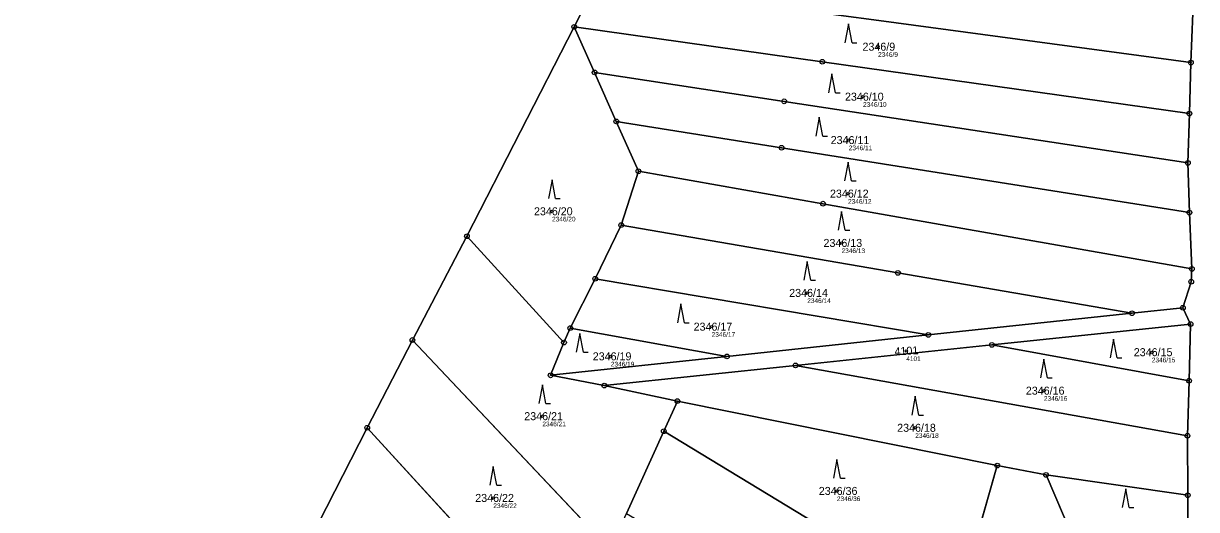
# Model space of a CAD drawing. Extents: x -658203 to -653176, y -1156738 to -1151709.
# Drawn here: x -657305.7 to -657056.4, y -1156494.1 to -1156390.7 of the extents above; entities that cross this region are included whole.
import ezdxf

# ---------------------------------------------------------------- set-up
doc = ezdxf.new("R2010")
doc.units = 0
for name, color, linetype in [('Vrstva 1', 7, 'Continuous'), ('Vrstva 2', 7, 'Continuous'), ('Vrstva 3', 7, 'Continuous'), ('Vrstva 50', 7, 'Continuous'), ('Vrstva 51', 7, 'Continuous'), ('Vrstva 8', 7, 'Continuous')]:
    doc.layers.add(name, color=color, linetype=linetype)

msp = doc.modelspace()

# ---------------------------------------------------------------- linework, layer by layer
at = {"layer": 'Vrstva 1'}
for p, q in [((-657188.62, -1156391.4), (-657183.91, -1156382.03)), ((-657057.61, -1156399.01), (-657057.22, -1156388.52)), ((-657211.43, -1156435.94), (-657188.62, -1156391.4)), ((-657188.62, -1156391.4), (-657184.31, -1156401.1)), ((-657057.94, -1156409.86), (-657057.61, -1156399.01)), ((-657184.31, -1156401.1), (-657179.69, -1156411.51)), ((-657058.25, -1156420.34), (-657057.94, -1156409.86)), ((-657179.69, -1156411.51), (-657174.98, -1156422.11)), ((-657057.94, -1156430.9), (-657058.25, -1156420.34)), ((-657178.65, -1156433.58), (-657174.98, -1156422.11)), ((-657057.41, -1156442.87), (-657057.94, -1156430.9)), ((-657184.17, -1156444.97), (-657178.65, -1156433.58)), ((-657223, -1156458.01), (-657211.43, -1156435.94)), ((-657211.43, -1156435.94), (-657190.81, -1156458.55)), ((-657189.48, -1156455.46), (-657184.17, -1156444.97)), ((-657184.17, -1156444.97), (-657113.4, -1156456.93)), ((-657113.4, -1156456.93), (-657070.13, -1156452.33)), ((-657070.13, -1156452.33), (-657059.32, -1156451.14)), ((-657059.32, -1156451.14), (-657057.68, -1156454.62)), ((-657190.81, -1156458.55), (-657189.48, -1156455.46)), ((-657189.48, -1156455.46), (-657156.18, -1156461.51)), ((-657057.68, -1156454.62), (-657099.89, -1156459.04)), ((-657057.68, -1156454.62), (-657058.01, -1156466.67)), ((-657232.62, -1156476.67), (-657223, -1156458.01)), ((-657223, -1156458.01), (-657180.99, -1156502.54)), ((-657156.18, -1156461.51), (-657113.4, -1156456.93)), ((-657193.65, -1156465.52), (-657190.81, -1156458.55)), ((-657099.89, -1156459.04), (-657141.61, -1156463.43)), ((-657099.89, -1156459.04), (-657058.01, -1156466.67)), ((-657193.65, -1156465.52), (-657156.18, -1156461.51)), ((-657182.24, -1156467.71), (-657193.65, -1156465.52)), ((-657141.61, -1156463.43), (-657182.24, -1156467.71)), ((-657058.35, -1156478.39), (-657141.61, -1156463.43)), ((-657182.24, -1156467.71), (-657166.72, -1156471)), ((-657058.01, -1156466.67), (-657058.35, -1156478.39)), ((-657169.61, -1156477.41), (-657166.72, -1156471)), ((-657166.72, -1156471), (-657098.74, -1156484.72)), ((-657242.97, -1156496.96), (-657232.62, -1156476.67)), ((-657232.62, -1156476.67), (-657190.41, -1156522.85)), ((-657177.52, -1156494.88), (-657169.61, -1156477.41)), ((-657107.43, -1156515.16), (-657169.61, -1156477.41)), ((-657058.29, -1156491.02), (-657058.35, -1156478.39)), ((-657107.43, -1156515.16), (-657098.74, -1156484.72)), ((-657098.74, -1156484.72), (-657088.37, -1156486.71)), ((-657088.37, -1156486.71), (-657058.29, -1156491.02)), ((-657082.19, -1156501.18), (-657088.37, -1156486.71)), ((-657058.3, -1156504.54), (-657058.29, -1156491.02))]:
    msp.add_line(p, q, dxfattribs=at)
for points in [[(-657183.91, -1156382.03), (-657123.93, -1156390.07), (-657057.61, -1156399.01)], [(-657188.62, -1156391.4), (-657135.93, -1156398.82), (-657057.94, -1156409.86)], [(-657184.31, -1156401.1), (-657144.02, -1156407.24), (-657058.25, -1156420.34)], [(-657179.69, -1156411.51), (-657144.58, -1156417.1), (-657057.94, -1156430.9)], [(-657174.98, -1156422.11), (-657135.79, -1156429.01), (-657057.41, -1156442.87)], [(-657178.65, -1156433.58), (-657119.87, -1156443.72), (-657070.13, -1156452.33)], [(-657057.41, -1156442.87), (-657057.54, -1156445.6), (-657059.32, -1156451.14)]]:
    msp.add_lwpolyline(points, dxfattribs=at)
at = {"layer": 'Vrstva 3'}
for p, q in [((-657130.36, -1156390.77), (-657131.11, -1156394.77)), ((-657129.61, -1156394.77), (-657130.36, -1156390.77)), ((-657129.61, -1156394.77), (-657128.61, -1156394.77)), ((-657133.87, -1156401.4), (-657134.62, -1156405.4)), ((-657133.12, -1156405.4), (-657133.87, -1156401.4)), ((-657133.12, -1156405.4), (-657132.12, -1156405.4)), ((-657136.58, -1156410.63), (-657137.33, -1156414.63)), ((-657135.83, -1156414.63), (-657136.58, -1156410.63)), ((-657135.83, -1156414.63), (-657134.83, -1156414.63)), ((-657130.46, -1156420.17), (-657131.21, -1156424.17)), ((-657129.71, -1156424.17), (-657130.46, -1156420.17)), ((-657193.35, -1156423.93), (-657194.1, -1156427.93)), ((-657192.6, -1156427.93), (-657193.35, -1156423.93)), ((-657129.71, -1156424.17), (-657128.71, -1156424.17)), ((-657192.6, -1156427.93), (-657191.6, -1156427.93)), ((-657131.83, -1156430.66), (-657132.58, -1156434.66)), ((-657131.08, -1156434.66), (-657131.83, -1156430.66)), ((-657131.08, -1156434.66), (-657130.08, -1156434.66)), ((-657139.12, -1156441.29), (-657139.87, -1156445.29)), ((-657138.37, -1156445.29), (-657139.12, -1156441.29)), ((-657138.37, -1156445.29), (-657137.37, -1156445.29)), ((-657165.97, -1156450.32), (-657166.72, -1156454.32)), ((-657165.22, -1156454.32), (-657165.97, -1156450.32)), ((-657165.22, -1156454.32), (-657164.22, -1156454.32)), ((-657187.44, -1156456.63), (-657188.19, -1156460.63)), ((-657186.69, -1156460.63), (-657187.44, -1156456.63)), ((-657074.04, -1156457.8), (-657074.79, -1156461.8)), ((-657073.29, -1156461.8), (-657074.04, -1156457.8)), ((-657186.69, -1156460.63), (-657185.69, -1156460.63)), ((-657088.84, -1156462.08), (-657089.59, -1156466.08)), ((-657088.09, -1156466.08), (-657088.84, -1156462.08)), ((-657073.29, -1156461.8), (-657072.29, -1156461.8)), ((-657195.41, -1156467.51), (-657196.16, -1156471.51)), ((-657194.66, -1156471.51), (-657195.41, -1156467.51)), ((-657088.09, -1156466.08), (-657087.09, -1156466.08)), ((-657116.18, -1156469.98), (-657116.93, -1156473.98)), ((-657115.43, -1156473.98), (-657116.18, -1156469.98)), ((-657194.66, -1156471.51), (-657193.66, -1156471.51)), ((-657115.43, -1156473.98), (-657114.43, -1156473.98)), ((-657205.83, -1156484.9), (-657206.58, -1156488.9)), ((-657205.08, -1156488.9), (-657205.83, -1156484.9)), ((-657132.83, -1156483.41), (-657133.58, -1156487.41)), ((-657132.08, -1156487.41), (-657132.83, -1156483.41)), ((-657132.08, -1156487.41), (-657131.08, -1156487.41)), ((-657205.08, -1156488.9), (-657204.08, -1156488.9)), ((-657071.45, -1156489.64), (-657072.2, -1156493.64)), ((-657070.7, -1156493.64), (-657071.45, -1156489.64)), ((-657070.7, -1156493.64), (-657069.7, -1156493.64))]:
    msp.add_line(p, q, dxfattribs=at)
at = {"layer": 'Vrstva 50'}
for centre in [(-657124.08, -1156395.62), (-657127.27, -1156406.25), (-657130.31, -1156415.48), (-657130.46, -1156426.87), (-657193.35, -1156430.63), (-657131.83, -1156437.36), (-657139.12, -1156447.99), (-657159.43, -1156455.17), (-657118.08, -1156460.32), (-657065.91, -1156460.6), (-657180.86, -1156461.48), (-657088.84, -1156468.78), (-657195.41, -1156474.21), (-657116.18, -1156476.68), (-657132.83, -1156490.11), (-657205.83, -1156491.6)]:
    msp.add_circle(centre, 0.25, dxfattribs=at)
at = {"layer": 'Vrstva 51'}
for points in [[(-657305.98, -1156615.34), (-657289.16, -1156587.16), (-657266.54, -1156540.38), (-657254.65, -1156518.63), (-657242.97, -1156496.96), (-657232.62, -1156476.67), (-657223, -1156458.01), (-657211.43, -1156435.94), (-657188.62, -1156391.4), (-657183.91, -1156382.03), (-657178.68, -1156371.93), (-657173.5, -1156361.77), (-657167.63, -1156350.41), (-657161.36, -1156338.39), (-657154.69, -1156325.52), (-657148.04, -1156312.63), (-657140.18, -1156297.75), (-657125.84, -1156270.51), (-657103.23, -1156287.36), (-657087.67, -1156287.89), (-657063.91, -1156290.69), (-657057.89, -1156290.12), (-657056.44, -1156227.83), (-657082.93, -1156177.03)], [(-657057.22, -1156388.52), (-657057.61, -1156399.01), (-657057.94, -1156409.86), (-657058.25, -1156420.34), (-657057.94, -1156430.9), (-657057.41, -1156442.87), (-657057.54, -1156445.6), (-657059.32, -1156451.14), (-657057.68, -1156454.62), (-657058.01, -1156466.67), (-657058.35, -1156478.39), (-657058.29, -1156491.02), (-657058.3, -1156504.54), (-657058.48, -1156523.84), (-657064.22, -1156587.9), (-657064.82, -1156589.86), (-657061.27, -1156586.81), (-657058.54, -1156584.34), (-657054.23, -1156524.63)]]:
    msp.add_lwpolyline(points, dxfattribs=at)
for points in [[(-657183.91, -1156382.03), (-657123.93, -1156390.07), (-657057.61, -1156399.01), (-657057.22, -1156388.52), (-657110.53, -1156381.22), (-657178.68, -1156371.93)], [(-657057.94, -1156409.86), (-657057.61, -1156399.01), (-657123.93, -1156390.07), (-657183.91, -1156382.03), (-657188.62, -1156391.4), (-657135.93, -1156398.82)], [(-657189.48, -1156455.46), (-657184.17, -1156444.97), (-657178.65, -1156433.58), (-657174.98, -1156422.11), (-657179.69, -1156411.51), (-657184.31, -1156401.1), (-657188.62, -1156391.4), (-657211.43, -1156435.94), (-657190.81, -1156458.55)], [(-657184.31, -1156401.1), (-657144.02, -1156407.24), (-657058.25, -1156420.34), (-657057.94, -1156409.86), (-657135.93, -1156398.82), (-657188.62, -1156391.4)], [(-657057.94, -1156430.9), (-657058.25, -1156420.34), (-657144.02, -1156407.24), (-657184.31, -1156401.1), (-657179.69, -1156411.51), (-657144.58, -1156417.1)], [(-657057.41, -1156442.87), (-657057.94, -1156430.9), (-657144.58, -1156417.1), (-657179.69, -1156411.51), (-657174.98, -1156422.11), (-657135.79, -1156429.01)], [(-657070.13, -1156452.33), (-657059.32, -1156451.14), (-657057.54, -1156445.6), (-657057.41, -1156442.87), (-657135.79, -1156429.01), (-657174.98, -1156422.11), (-657178.65, -1156433.58), (-657119.87, -1156443.72)], [(-657113.4, -1156456.93), (-657070.13, -1156452.33), (-657119.87, -1156443.72), (-657178.65, -1156433.58), (-657184.17, -1156444.97)], [(-657169.61, -1156477.41), (-657166.72, -1156471), (-657182.24, -1156467.71), (-657193.65, -1156465.52), (-657190.81, -1156458.55), (-657211.43, -1156435.94), (-657223, -1156458.01), (-657180.99, -1156502.54), (-657177.52, -1156494.88)], [(-657156.18, -1156461.51), (-657113.4, -1156456.93), (-657184.17, -1156444.97), (-657189.48, -1156455.46)], [(-657182.24, -1156467.71), (-657141.61, -1156463.43), (-657099.89, -1156459.04), (-657057.68, -1156454.62), (-657059.32, -1156451.14), (-657070.13, -1156452.33), (-657113.4, -1156456.93), (-657156.18, -1156461.51), (-657193.65, -1156465.52)], [(-657193.65, -1156465.52), (-657156.18, -1156461.51), (-657189.48, -1156455.46), (-657190.81, -1156458.55)], [(-657099.89, -1156459.04), (-657058.01, -1156466.67), (-657057.68, -1156454.62)], [(-657180.99, -1156502.54), (-657223, -1156458.01), (-657232.62, -1156476.67), (-657190.41, -1156522.85), (-657184.85, -1156511.08)], [(-657141.61, -1156463.43), (-657058.35, -1156478.39), (-657058.01, -1156466.67), (-657099.89, -1156459.04)], [(-657058.29, -1156491.02), (-657058.35, -1156478.39), (-657141.61, -1156463.43), (-657182.24, -1156467.71), (-657166.72, -1156471), (-657098.74, -1156484.72), (-657088.37, -1156486.71)], [(-657098.74, -1156484.72), (-657166.72, -1156471), (-657169.61, -1156477.41), (-657107.43, -1156515.16)], [(-657200.53, -1156545.91), (-657199.45, -1156543.36), (-657192.5, -1156528), (-657190.41, -1156522.85), (-657232.62, -1156476.67), (-657242.97, -1156496.96)], [(-657112.4, -1156532.83), (-657109.5, -1156522.45), (-657107.43, -1156515.16), (-657169.61, -1156477.41), (-657177.52, -1156494.88)], [(-657088.37, -1156486.71), (-657098.74, -1156484.72), (-657107.43, -1156515.16), (-657109.5, -1156522.45), (-657062.3, -1156546.98), (-657072.65, -1156522.9), (-657082.19, -1156501.18)], [(-657058.3, -1156504.54), (-657058.29, -1156491.02), (-657088.37, -1156486.71), (-657082.19, -1156501.18)]]:
    msp.add_lwpolyline(points, close=True, dxfattribs=at)
at = {"layer": 'Vrstva 8'}
for centre, radius in [((-657188.62, -1156391.4), 0.5), ((-657188.62, -1156391.4), 0.0303), ((-657135.93, -1156398.82), 0.5), ((-657057.61, -1156399.01), 0.5), ((-657184.31, -1156401.1), 0.5), ((-657135.93, -1156398.82), 0.0303), ((-657057.61, -1156399.01), 0.0303), ((-657184.31, -1156401.1), 0.0303), ((-657144.02, -1156407.24), 0.5), ((-657144.02, -1156407.24), 0.0303), ((-657057.94, -1156409.86), 0.5), ((-657057.94, -1156409.86), 0.0303), ((-657179.69, -1156411.51), 0.5), ((-657179.69, -1156411.51), 0.0303), ((-657144.58, -1156417.1), 0.5), ((-657144.58, -1156417.1), 0.0303), ((-657058.25, -1156420.34), 0.5), ((-657058.25, -1156420.34), 0.0303), ((-657174.98, -1156422.11), 0.5), ((-657174.98, -1156422.11), 0.0303), ((-657135.79, -1156429.01), 0.5), ((-657135.79, -1156429.01), 0.0303), ((-657057.94, -1156430.9), 0.5), ((-657057.94, -1156430.9), 0.0303), ((-657178.65, -1156433.58), 0.5), ((-657211.43, -1156435.94), 0.5), ((-657211.43, -1156435.94), 0.0303), ((-657178.65, -1156433.58), 0.0303), ((-657119.87, -1156443.72), 0.5), ((-657057.41, -1156442.87), 0.5), ((-657057.41, -1156442.87), 0.0303), ((-657184.17, -1156444.97), 0.5), ((-657184.17, -1156444.97), 0.0303), ((-657119.87, -1156443.72), 0.0303), ((-657057.54, -1156445.6), 0.5), ((-657057.54, -1156445.6), 0.0303), ((-657059.32, -1156451.14), 0.5), ((-657070.13, -1156452.33), 0.5), ((-657070.13, -1156452.33), 0.0303), ((-657059.32, -1156451.14), 0.0303), ((-657189.48, -1156455.46), 0.5), ((-657189.48, -1156455.46), 0.0303), ((-657057.68, -1156454.62), 0.5), ((-657057.68, -1156454.62), 0.0303), ((-657223, -1156458.01), 0.5), ((-657223, -1156458.01), 0.0303), ((-657190.81, -1156458.55), 0.5), ((-657113.4, -1156456.93), 0.5), ((-657113.4, -1156456.93), 0.0303), ((-657190.81, -1156458.55), 0.0303), ((-657099.89, -1156459.04), 0.5), ((-657099.89, -1156459.04), 0.0303), ((-657156.18, -1156461.51), 0.5), ((-657156.18, -1156461.51), 0.0303), ((-657141.61, -1156463.43), 0.5), ((-657193.65, -1156465.52), 0.5), ((-657193.65, -1156465.52), 0.0303), ((-657141.61, -1156463.43), 0.0303), ((-657182.24, -1156467.71), 0.5), ((-657182.24, -1156467.71), 0.0303), ((-657058.01, -1156466.67), 0.5), ((-657058.01, -1156466.67), 0.0303), ((-657166.72, -1156471), 0.5), ((-657166.72, -1156471), 0.0303), ((-657232.62, -1156476.67), 0.5), ((-657232.62, -1156476.67), 0.0303), ((-657169.61, -1156477.41), 0.5), ((-657169.61, -1156477.41), 0.0303), ((-657058.35, -1156478.39), 0.5), ((-657058.35, -1156478.39), 0.0303), ((-657098.74, -1156484.72), 0.5), ((-657098.74, -1156484.72), 0.0303), ((-657088.37, -1156486.71), 0.5), ((-657088.37, -1156486.71), 0.0303), ((-657058.29, -1156491.02), 0.5), ((-657058.29, -1156491.02), 0.0303)]:
    msp.add_circle(centre, radius, dxfattribs=at)

# ---------------------------------------------------------------- texts
at = {"layer": 'Vrstva 2'}
for s, p in [('2346/9', (-657127.39, -1156396.47)), ('2346/10', (-657131.11, -1156407.1)), ('2346/11', (-657134.15, -1156416.33)), ('2346/12', (-657134.3, -1156427.72)), ('2346/20', (-657197.19, -1156431.48)), ('2346/13', (-657135.67, -1156438.21)), ('2346/14', (-657142.96, -1156448.84)), ('2346/17', (-657163.27, -1156456.02)), ('2346/19', (-657184.7, -1156462.33)), ('2346/15', (-657069.75, -1156461.45)), ('2346/16', (-657092.68, -1156469.63)), ('2346/21', (-657199.25, -1156475.06)), ('2346/18', (-657120.02, -1156477.53)), ('2346/22', (-657209.67, -1156492.45)), ('2346/36', (-657136.67, -1156490.96))]:
    msp.add_text(s, height=1.7, dxfattribs=at).set_placement(p)
msp.add_text('4101', height=1.7, rotation=3, dxfattribs=at).set_placement((-657120.54, -1156461.3))
at = {"layer": 'Vrstva 50'}
for s, p in [('2346/9', (-657124.08, -1156397.78)), ('2346/10', (-657127.27, -1156408.41)), ('2346/11', (-657130.31, -1156417.64)), ('2346/12', (-657130.46, -1156429.03)), ('2346/20', (-657193.35, -1156432.79)), ('2346/13', (-657131.83, -1156439.52)), ('2346/14', (-657139.12, -1156450.15)), ('2346/17', (-657159.43, -1156457.33)), ('2346/19', (-657180.86, -1156463.64)), ('4101', (-657118.08, -1156462.48)), ('2346/15', (-657065.91, -1156462.76)), ('2346/16', (-657088.84, -1156470.94)), ('2346/21', (-657195.41, -1156476.37)), ('2346/18', (-657116.18, -1156478.84)), ('2346/22', (-657205.83, -1156493.76)), ('2346/36', (-657132.83, -1156492.27))]:
    msp.add_text(s, height=1, dxfattribs=at).set_placement(p)

doc.saveas('drawing.dxf')
